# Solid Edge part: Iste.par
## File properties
Author: Georg
Template: Iso Part.par
Last saved by: Kalle
Revision: 5
Application: Solid Edge
Accuracy: 0,990
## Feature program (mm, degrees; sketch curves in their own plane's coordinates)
sketch for "unnamed Protrusion 1" plane through (0, 0, 0) normal (0, 0, 1) x-axis (1, 0, 0)
extrude "unnamed Protrusion 1" add finite 6 along +normal
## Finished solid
Body 1: solid body, 6 faces, 12 edges, 8 vertices.
  Faces by surface: plane 6
  Edges by curve: line 12
Bounding box of the edges (mm): 15.000 x 15.000 x 6.000, from (-7.5, -7.5, 0) to (7.5, 7.5, 6).
Planar faces by outward normal: +x 1, +y 1, +z 1, -x 1, -y 1, -z 1
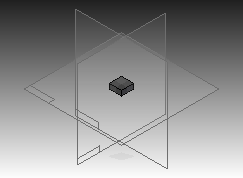
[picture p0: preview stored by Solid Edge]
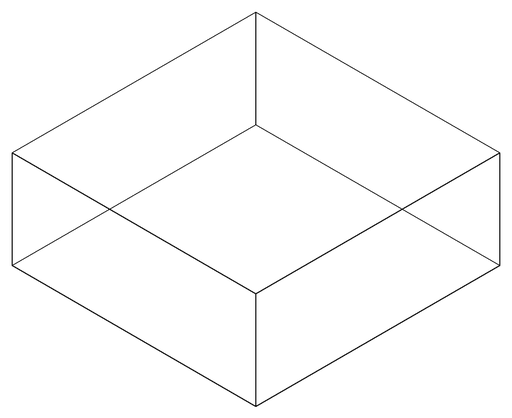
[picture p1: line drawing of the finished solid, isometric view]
